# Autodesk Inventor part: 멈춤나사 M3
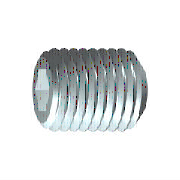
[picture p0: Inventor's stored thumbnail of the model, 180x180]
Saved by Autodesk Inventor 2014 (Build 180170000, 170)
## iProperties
IsCustomPart: 1
Created: 2012-02
Part Number: 멈춤나사 M3
Material: 강철, 연강
Description: 6각 소켓 머리 없는 멈춤 나사
Document SubType Name: Modeling
Standard: KS B 1028
Designer: mduedu
Standards Organization: KS
Language: ko-KR
Size Designation: 납작점M3x8
Categories: <MemberInstance><Categories><Category DisplayName="조임쇠" InternalName="e4da775c-781d-43d5-af7c-5136215cf5a6" Mnemonic="FSTN"><Category DisplayName="볼트" InternalN
Density: 1 g/cm^3
Appearance: Steel
Author: mduedu
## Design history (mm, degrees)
sketch "스케치1"
  geometry: L1 (0, 0)-(5.5, 0); L2 (8, 0.866)-(8, 1.5); L3 (8, 1.5)-(0, 1.5); L4 (8, 0.866)-(6, 0.866); L5 (6, 0.866)-(5.5, 0); L6 (0, -0.3)-(0, 1.8) reference; L7 (0, 1.5)-(0, 0)
  constraints: 13 end point, 3 parallel, 1 collinear, 1 perpendicular, 1 point on line
  dimensions: "d0" = 2 distance of L2.start L4.end (= INTI); "d1" = 60 deg angle of L5 L1; "d2" = 3 diameter of L3 L1 (= NND); "d3" = 1.73205 diameter of L4 L1 (= 1.1547 x SW); "d5" = 8 distance from line of L2 L3.end (= NLG)
revolve "본체" sketch "스케치1" stored, may be unused: angle "d6" = 90 deg
sketch "스케치2"
  geometry: L1 (-0.433, 0.75)-(0.433, 0.75); L2 (0.433, 0.75)-(0.866, 0); L3 (0.866, 0)-(0.433, -0.75); L4 (0.433, -0.75)-(-0.433, -0.75); L5 (-0.433, -0.75)-(-0.866, 0); L6 (-0.866, 0)-(-0.433, 0.75); A1 r 0.866 centre (0, 0) between (-0.433, 0.75) and (0.433, 0.75) reference; 2 further points
  constraints: 12 end point, 2 point on circle, 1 coincident, 1 horizontal, 11 other
extrude "슬롯" join sketch "스케치2" taper "d9" = 0 deg; stored distance "d21" = 10
workaxis "Work Axis1"
workplane "Work Plane1"
body "Solid1"
chamfer "모따기1" distance "d7" = 0.30673 (= -0.5 x GD1 + 0.5 x NND); stored, may be unused: angle "d8" = 45 deg (= FAWI), second distance "d29" = 0.30673 (= -0.5 x GD1 + 0.5 x NND)
feature "스레드" dims "d11" = 8 (= NLG), "d12" = 0
chamfer "모따기2" distance "d13" = 0.30673 (= -0.5 x GD1 + 0.5 x NND); stored, may be unused: angle "d14" = 45 deg (= FAWI), second distance "d30" = 0.30673 (= -0.5 x GD1 + 0.5 x NND)
other parameters: "NND" = 3 [user parameter; used in 5 equation terms], "NLG" = 8 [user parameter; used in 2 equation terms], "INTI" = 2 [user parameter; used in 1 equation term], "FAWI" = 45 deg [user parameter; used in 2 equation terms], "SW" = 1.5 [user parameter; used in 2 equation terms], "GD1" = 2.38655 (= THREADDIA - 1.2269 x PTC) [user parameter; used in 4 equation terms], "d4" = 0, "FAWI1" = 45 deg [user parameter], "d15" = 0, "d31" = 0, "GUL" = 0.30673 (= 0.61345 x PTC) [user parameter], "SPD" = 2 [user parameter], "TOA" = 30 deg [user parameter], "THREADDIA" = 3 [user parameter; used in 1 equation term], "PTC" = 0.5 [user parameter; used in 4 equation terms], "GAL" = 0.30673 (= 0.61345 x PTC) [user parameter], "E0" = 1.7325 (= 1.155 x SW) [user parameter]
